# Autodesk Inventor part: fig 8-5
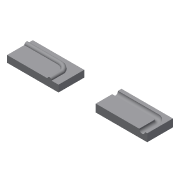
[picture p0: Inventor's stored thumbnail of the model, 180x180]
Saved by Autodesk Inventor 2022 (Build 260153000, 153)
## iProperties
Created: 2009-04
Part Number: fig 8-5
Document SubType Name: Modeling
Designer: Sham
Density: 1 g/cm^3
Material: Generic
Appearance: Default
Author: Sham
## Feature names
1. Extrusion1
2. Sweep5
3. Extrusion2
4. Sweep6
## Parameters: d0 = 6 mm, d1 = 0, d6 = 0, d7 = 5.25 mm, d8 = 0, d9 = 0, d10 = 0, d11 = 0
